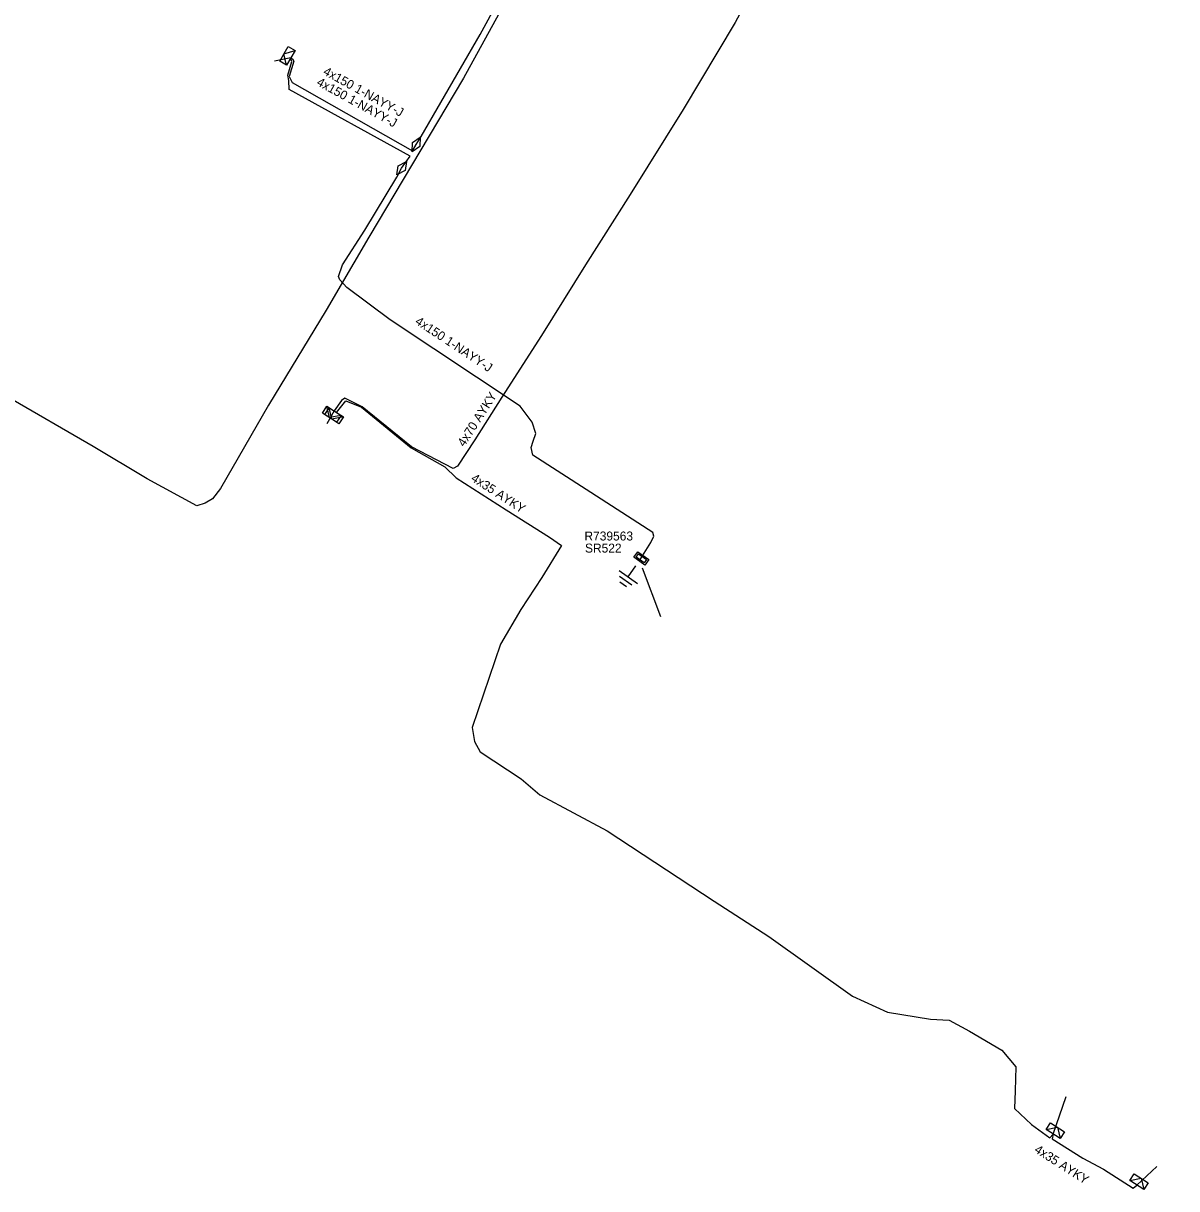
# Model space of a CAD drawing. Extents: x -540028 to -538776, y -1157064 to -1155670.
# Drawn here: x -539322.6 to -539193.8, y -1155928.9 to -1155798.8 of the extents above; entities that cross this region are included whole.
import ezdxf

# ---------------------------------------------------------------- set-up
doc = ezdxf.new("R2010")
doc.units = 0
for name, color, linetype in [('Vrstva 15', 7, 'Continuous'), ('Vrstva 19', 7, 'Continuous'), ('Vrstva 2', 7, 'Continuous'), ('Vrstva 28', 7, 'Continuous'), ('Vrstva 29', 7, 'Continuous'), ('Vrstva 30', 7, 'Continuous'), ('Vrstva 31', 7, 'Continuous'), ('Vrstva 5', 7, 'Continuous'), ('Vrstva 59', 7, 'Continuous'), ('Vrstva 6', 7, 'Continuous')]:
    doc.layers.add(name, color=color, linetype=linetype)

# ---------------------------------------------------------------- blocks, each defined once
blk = doc.blocks.new('17')
at = {"layer": 'Vrstva 2'}
blk.add_lwpolyline([(-1.875, 0), (0, 0.9375), (1.875, 0), (0, -0.9375)], close=True, dxfattribs=at)
blk = doc.blocks.new('132')
at = {"layer": 'Vrstva 2'}
for points in [[(-1.5, 1.5), (1.5, 1.5), (1.5, 0), (-1.5, 0)], [(-1.1, 1.2), (1.1, 1.2), (1.1, 0.3), (-1.1, 0.3)]]:
    blk.add_lwpolyline(points, close=True, dxfattribs=at)
blk = doc.blocks.new('23')
at = {"layer": 'Vrstva 2'}
blk.add_lwpolyline([(1.875, -1.8), (-1.875, -1.8), (-1.875, 0), (1.875, 0)], close=True, dxfattribs=at)
blk.add_lwpolyline([(1.875, 0), (0, -1.8), (-1.875, 0)], dxfattribs=at)
blk = doc.blocks.new('11')
at = {"layer": 'Vrstva 2'}
for p, q in [((0, -4.3), (0, -1.3)), ((-2.5, -4.3), (2.5, -4.3)), ((-1.7, -5.3), (1.7, -5.3)), ((-0.9, -6.3), (0.9, -6.3))]:
    blk.add_line(p, q, dxfattribs=at)

msp = doc.modelspace()

# ---------------------------------------------------------------- linework, layer by layer
at = {"layer": 'Vrstva 5'}
for points in [[(-539223.28, -1155719.26), (-539230.33, -1155731.85), (-539237.2, -1155743.07), (-539243.97, -1155754.51), (-539251.76, -1155767.37), (-539258.93, -1155779.8), (-539265.81, -1155791.09), (-539273.41, -1155804.91), (-539284.01, -1155822.69), (-539288.74, -1155830.83), (-539295.21, -1155841.44), (-539300.56, -1155850.72), (-539301.46, -1155851.88), (-539302.26, -1155852.36), (-539303.21, -1155852.67), (-539308.77, -1155849.65), (-539314.79, -1155846.05), (-539324.41, -1155840.48)], [(-539192.27, -1155743.14), (-539201.17, -1155736.81), (-539203.79, -1155741.11), (-539209.21, -1155749.39), (-539213.43, -1155755.19), (-539219.77, -1155763.12), (-539232.36, -1155779.8), (-539235.17, -1155784.3), (-539240.34, -1155793.59), (-539243.08, -1155798.71), (-539248.89, -1155808.43), (-539254.81, -1155817.91), (-539259.8, -1155825.75), (-539264.72, -1155833.66), (-539269.12, -1155840.54), (-539272.15, -1155845.31), (-539274.08, -1155848.24), (-539274.59, -1155848.49), (-539279.21, -1155846.07), (-539284.75, -1155841.62), (-539286.66, -1155840.65), (-539287.04, -1155840.91), (-539287.88, -1155842.07)], [(-539278.7, -1155812.32), (-539278.15, -1155811.43), (-539271.57, -1155800.03), (-539267.67, -1155792.9)], [(-539280.33, -1155814.97), (-539279.37, -1155813.63), (-539292.88, -1155806.18), (-539292.92, -1155805.17), (-539293.04, -1155804.59), (-539292.58, -1155803.06), (-539292.68, -1155802.87), (-539292.7, -1155802.65), (-539292.51, -1155802.77), (-539292.36, -1155803.03), (-539292.88, -1155804.73), (-539292.56, -1155805.41), (-539279.11, -1155813.05), (-539278.7, -1155812.32)], [(-539253.78, -1155858.85), (-539252.48, -1155856.75), (-539252.16, -1155856.06), (-539252.27, -1155855.65), (-539259.72, -1155850.83), (-539265.69, -1155847.02), (-539265.86, -1155846.14), (-539265.63, -1155845.46), (-539265.34, -1155844.6), (-539265.74, -1155843.33), (-539267.08, -1155841.54), (-539281.61, -1155831.92), (-539286.45, -1155828.29), (-539287.25, -1155827.44), (-539287.37, -1155827.06), (-539286.95, -1155825.76), (-539284.44, -1155821.9), (-539280.85, -1155815.98), (-539280.33, -1155814.97)], [(-539287.88, -1155842.07), (-539287.62, -1155842.24), (-539286.58, -1155840.93), (-539284.8, -1155841.65), (-539279.27, -1155846.2), (-539275.49, -1155848.32), (-539274.23, -1155849.53), (-539268.67, -1155853.13), (-539263.83, -1155856.16), (-539262.48, -1155857.1), (-539264.68, -1155860.67), (-539267.02, -1155864.23), (-539269.29, -1155868.12), (-539272.46, -1155877.42), (-539272.18, -1155878.97), (-539271.56, -1155880.14), (-539266.99, -1155883.16), (-539264.89, -1155884.94), (-539257.38, -1155888.96), (-539245.43, -1155896.81), (-539239.33, -1155900.76), (-539229.97, -1155907.4), (-539226.05, -1155909.19), (-539221.26, -1155909.99), (-539219.16, -1155910.09), (-539216.9, -1155911.33), (-539213.28, -1155913.44), (-539211.73, -1155915.32), (-539211.8, -1155917.98), (-539211.86, -1155919.96), (-539209.98, -1155921.75), (-539207.91, -1155923.25), (-539207.55, -1155922.82), (-539207.65, -1155923.33), (-539204.23, -1155925.52), (-539201.92, -1155926.72), (-539198.61, -1155928.86), (-539198.21, -1155928.51)]]:
    msp.add_lwpolyline(points, dxfattribs=at)
at = {"layer": 'Vrstva 59'}
for points in [[(-539292.7, -1155802.65), (-539294.53, -1155803.02)], [(-539287.88, -1155842.07), (-539288.69, -1155843.53)], [(-539253.45, -1155859.6), (-539251.43, -1155865.01)], [(-539207.55, -1155922.82), (-539206.09, -1155918.61)], [(-539198.21, -1155928.51), (-539195.96, -1155926.43)]]:
    msp.add_lwpolyline(points, dxfattribs=at)

# ---------------------------------------------------------------- block references
at = {"layer": 'Vrstva 15', "xscale": 0.5, "yscale": 0.5, "rotation": -34.98562866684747}
msp.add_blockref('11', (-539253.78, -1155858.85), dxfattribs=at)
at = {"layer": 'Vrstva 19'}
for p, xscale, yscale, rotation in [((-539278.7, -1155812.32), 0.5, 0.5, -119.32047585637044), ((-539280.33, -1155814.97), 0.5000000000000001, 0.4999999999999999, 54.38151012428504)]:
    msp.add_blockref('17', p, dxfattribs=dict(at, xscale=xscale, yscale=yscale, rotation=rotation))
at = {"layer": 'Vrstva 28', "xscale": 0.5, "yscale": 0.5, "rotation": -34.98562866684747}
msp.add_blockref('132', (-539253.78, -1155858.85), dxfattribs=at)
at = {"layer": 'Vrstva 31', "xscale": 0.5}
for p, yscale, rotation in [((-539292.7, -1155802.65), 0.5, -120.20323769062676), ((-539287.88, -1155842.07), 0.5, -33.097713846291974), ((-539287.62, -1155842.24), 0.5, -33.097713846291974), ((-539207.55, -1155922.82), 0.5000000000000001, 148.01537221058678), ((-539198.21, -1155928.51), 0.5, 147.5433832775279)]:
    msp.add_blockref('23', p, dxfattribs=dict(at, yscale=yscale, rotation=rotation))

# ---------------------------------------------------------------- texts
at = {"layer": 'Vrstva 29'}
msp.add_text('R739563', height=1, dxfattribs=at).set_placement((-539259.91, -1155856.54))
at = {"layer": 'Vrstva 30'}
msp.add_text('SR522', height=1, dxfattribs=at).set_placement((-539259.85, -1155857.89))
at = {"layer": 'Vrstva 6'}
for s, rotation, p in [('4x150 1-NAYY-J', 331.126, (-539289.18, -1155804.46)), ('4x150 1-NAYY-J', 331.126, (-539289.91, -1155805.65)), ('4x150 1-NAYY-J', 326.492, (-539278.91, -1155832.29)), ('4x70 AYKY', 57.4, (-539273.33, -1155846.15)), ('4x35 AYKY', 327.078, (-539272.66, -1155849.82)), ('4x35 AYKY', 327.397, (-539209.74, -1155924.78))]:
    msp.add_text(s, height=1, rotation=rotation, dxfattribs=at).set_placement(p)

doc.saveas('drawing.dxf')
